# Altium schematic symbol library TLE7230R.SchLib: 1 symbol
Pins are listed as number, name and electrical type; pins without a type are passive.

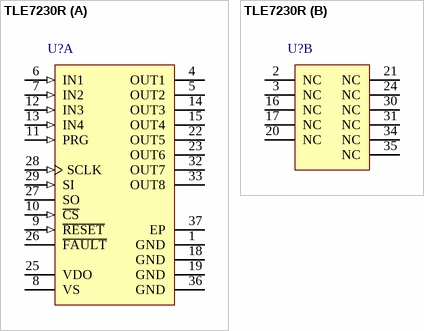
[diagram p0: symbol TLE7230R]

## TLE7230R
designator U?
Smart Octal Low-Side Switch, 10 uA Quiescent Current, 4.5 to 5.5 V VDD, -40 to 150 degC, PG-DSO-36-47, Reel, Green; Manufacturer: Infineon; PartNumber: TLE7230R; Channels: 8; Cranking mode: FALSE; Daisy-chain capability: TRUE; ID nom: 500 mA; ID(lim) (min): 1 A; Open Load Detection: off; Open Load Disable Function: FALSE; Overcurrent limitation or shutdown: Selectable; PWM Inputs: 4; Quiescent Current (max): 10 uA; RDS (on) (max): 1.7 Ohm; RDS (on) (typ): 0.8 Ohm; SPI: 16 Bit; VDD: 4.5 - 5.5 V; VDS(CL): 48 - 60 V
footprint INF-PG-DSO-36-47_N (SOP, 36-Leads, Body 15.9x11mm, Pitch 0.65mm, Thermal Pad 6X16mm, IPC Medium Density)
footprint INF-PG-DSO-36-47_L (SOP, 36-Leads, Body 15.9x11mm, Pitch 0.65mm, Thermal Pad 6X16mm, IPC High Density)
footprint INF-PG-DSO-36-47_M (SOP, 36-Leads, Body 15.9x11mm, Pitch 0.65mm, Thermal Pad 6X16mm, IPC Low Density)
part A pins: 1 GND (power) "Ground pins.", 4 OUT1 (power) "Drain pins of the 8 channels. Output pins to connect to loads.", 5 OUT2 (power) "Drain pins of the 8 channels. Output pins to connect to loads.", 6 IN1 (in) "Parallel Input Pins of the channels 1 to 3", 7 IN2 (in) "Parallel Input Pins of the channels 1 to 3", 8 VS (power) "Logic supply pin. This pin is used to supply the integrated circuitry.", 9 ~{RESET} (in) "If the reset pin is in a logic low state, it clears the SPI shift register and switches all outputs OFF. An internal pull-up structure is provided on chip.", 10 ~{CS} (in) "Chip Select of the Serial Peripheral Interface", 11 PRG (in) "Program pin. PRG = High (VS): Parallel inputs 1 to 4 are high active PRG = Low (GND): Parallel inputs 1 to 4 are low active. If the parallel input pins are not connected (independent of high or low activity) it is guaranteed (See Datasheet)", 12 IN3 (in) "Parallel Input Pins of the channels 1 to 3", 13 IN4 (in) "Mapable parallel Input Pin. Can be assigned to different outputs by SPI command. Default Output is OUT4", 14 OUT3 (power) "Drain pins of the 8 channels. Output pins to connect to loads.", 15 OUT4 (power) "Drain pins of the 8 channels. Output pins to connect to loads.", 18 GND (power) "Ground pins.", 19 GND (power) "Ground pins.", 22 OUT5 (power) "Drain pins of the 8 channels. Output pins to connect to loads.", 23 OUT6 (power) "Drain pins of the 8 channels. Output pins to connect to loads.", 25 VDO (power) "Supply pin of the Signal Output (SO) pin of the SPI interface . This pin can be used to vary the high-state output voltage of the SO pin.", 26 ~{FAULT} (oc) "There is a general fault pin (open drain) which shows a high to low transition as soon as an error occurs at any one of the eight channels. This fault indication can be used to generate a uC interrupt. Therefore a (See Datasheet)", 27 SO (hiz) "Signal Output of the Serial Peripheral Interface", 28 SCLK (in) "Clock Input of the Serial Peripheral Interface. The pin has an internal pull down structure", 29 SI (in) "Signal Input of the Serial Peripheral Interface. The pin has an internal pull down structure.", 32 OUT7 (power) "Drain pins of the 8 channels. Output pins to connect to loads.", 33 OUT8 (power) "Drain pins of the 8 channels. Output pins to connect to loads.", 36 GND (power) "Ground pins.", 37 EP (power)
part B pins: 2 NC "not connected", 3 NC "not connected", 16 NC "not connected", 17 NC "not connected", 20 NC "not connected", 21 NC "not connected", 24 NC "not connected", 30 NC "not connected", 31 NC "not connected", 34 NC "not connected", 35 NC "not connected"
